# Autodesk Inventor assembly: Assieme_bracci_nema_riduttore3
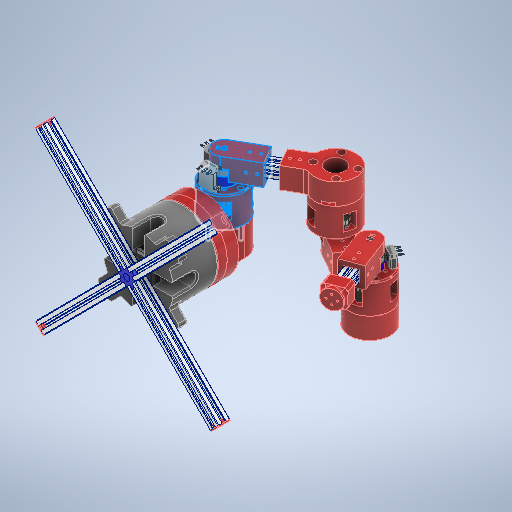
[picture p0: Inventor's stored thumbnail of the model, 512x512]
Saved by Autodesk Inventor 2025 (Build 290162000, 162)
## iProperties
Created: 2026-01
Part Number: Assieme_bracci_nema_riduttore3
Document SubType Name: Assembly
Designer: Ryzen5700u
Author: Ryzen5700u
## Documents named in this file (22)
- C:\Users\Ryzen5700u\Desktop\antropomorfo_nema5\Assieme_bracci_nema_riduttore4.iam
- C:\Users\Ryzen5700u\Desktop\antropomorfo_nema5\blocco_nema_riduttore.iam
- C:\Users\Ryzen5700u\Desktop\antropomorfo_nema5\blocco_nema2.ipt
- C:\Users\Ryzen5700u\Desktop\antropomorfo_nema5\blocco_nema_riduttore2.iam
- C:\Users\Ryzen5700u\Desktop\antropomorfo_nema5\blocco_base.ipt
- C:\Users\Ryzen5700u\Desktop\antropomorfo_nema5\tslot-20x20-5.ipt
- C:\Users\Ryzen5700u\Desktop\antropomorfo_nema5\terminale.ipt
- C:\Users\Ryzen5700u\Desktop\antropomorfo_nema5\NEMA 17HS4401S-PG518.ipt
- C:\Users\Ryzen5700u\Desktop\antropomorfo_nema5\base_01.ipt
- C:\Users\Ryzen5700u\Desktop\antropomorfo_nema5\maschera.ipt
- C:\Users\Ryzen5700u\Desktop\antropomorfo_nema5\ISO 104 - 1 11 50 x 70 x 14.ipt
- C:\Users\Ryzen5700u\Desktop\antropomorfo_nema5\blocco_alto_base.ipt
- C:\Users\Ryzen5700u\Documents\Inventor\Content Center Files\R2025\it-IT\AS 1112 (2)\AS 1112 - M5  Tipo 5.ipt
- C:\Users\Ryzen5700u\Desktop\antropomorfo_nema5\ANSI B18.3.1M - M5x0,8 x 30(1).ipt
- C:\Users\Ryzen5700u\Desktop\antropomorfo_nema5\Assieme_tappo_tslot.iam
- C:\Users\Ryzen5700u\Desktop\antropomorfo_nema5\tslot-20x20-4.ipt
- C:\Users\Ryzen5700u\Documents\Inventor\Content Center Files\R2025\it-IT\ANSI B18.3.1M(6)\ANSI B18.3.1M - M5x0,8 x 16(1).ipt
- C:\Users\Ryzen5700u\Desktop\antropomorfo_nema5\Microswitch-SS-3GL13SL\Microswitch-SS-3GL13SL.iam
- C:\Users\Ryzen5700u\Desktop\antropomorfo_nema5\blocco_finecorsa.ipt
- C:\Users\Ryzen5700u\Desktop\antropomorfo_nema5\blocco_finecorsa2.ipt
- C:\Users\Ryzen5700u\Desktop\antropomorfo_nema5\blocco_finecorsa3.ipt
- C:\Users\Ryzen5700u\Desktop\antropomorfo_nema5\b_sensore_1.ipt
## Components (36 placed, 21 different names)
1. tslot-20x20-4:2 — Coincidente:12, Coincidente:13, Coincidente:14, Coincidente:26, Coincidente:27, Coincidente:28
2. blocco_nema_riduttore2:3 [sub-assembly] — Coincidente:38, Coincidente:41, Coincidente:43, Coincidente:44, Coincidente:45, Coincidente:46, Rotazionale:7
3. blocco_nema_riduttore:2 [sub-assembly]
4. blocco_base:1
5. tslot-20x20-5:1 — Coincidente:32, Coincidente:33, Coincidente:34, Coincidente:35, Coincidente:36, Coincidente:37
6. blocco_nema2:1
7. blocco_nema_riduttore2:4 [sub-assembly]
8. blocco_nema2:2 — Coincidente:35, Coincidente:36, Coincidente:37, Coincidente:38, Coincidente:41, Coincidente:46, Angolo:10
9. tslot-20x20-4:1 — Coincidente:43, Coincidente:44, Coincidente:45, Coincidente:47, Coincidente:48, Coincidente:49
10. terminale:1 — Coincidente:47, Coincidente:48, Coincidente:49
11. NEMA 17HS4401S-PG518:1 — Angolo:3, Coincidente:56, Coincidente:57
12. base_01:1
13. maschera:1
14. UNI ISO 104 1 11 50 x 70 x 14:2 — Rotazionale:4, Coincidente:54
15. blocco_alto_base:2 — Coincidente:54, Coincidente:55, Angolo:5, Coincidente:59
16. Vite forgiata a testa incassata - Metrico M5x0,8 x 30:1
17. Vite forgiata a testa incassata - Metrico M5x0,8 x 30:2
18. Vite forgiata a testa incassata - Metrico M5x0,8 x 30:3
19. Vite forgiata a testa incassata - Metrico M5x0,8 x 30:4
20. Vite forgiata a testa incassata - Metrico M5x0,8 x 16:1
21. Vite forgiata a testa incassata - Metrico M5x0,8 x 16:4
22. Vite forgiata a testa incassata - Metrico M5x0,8 x 16:2
23. Vite forgiata a testa incassata - Metrico M5x0,8 x 16:3
24. Assieme_tappo_tslot:1 [sub-assembly] — Coincidente:60, Coincidente:61
25. Microswitch-SS-3GL13SL:1 [sub-assembly] — Angolo:6, Coincidente:62, Allineato:1, Allineato:2
26. blocco_finecorsa:1 — Rotazionale:5, Coincidente:62, Allineato:1, Allineato:2
27. blocco_finecorsa2:1 — Rotazionale:6, Coincidente:63, Angolo:9, Allineato:3, Allineato:4, Angolo:11
28. Microswitch-SS-3GL13SL:2 [sub-assembly] — Coincidente:63, Angolo:9, Allineato:3, Allineato:4
29. blocco_finecorsa3:1 — Rotazionale:7, Coincidente:64, Coincidente:65, Coincidente:66, Angolo:10
30. Microswitch-SS-3GL13SL:3 [sub-assembly] — Coincidente:64, Coincidente:65, Coincidente:66
31. b_sensore_1:3 — Rotazionale:8, Coincidente:67, Angolo:12, Allineato:5, Coincidente:68
32. Microswitch-SS-3GL13SL:4 [sub-assembly] — Coincidente:67, Angolo:12, Allineato:5, Coincidente:68
33. AS 1112 (2) - Metrico M5  Tipo 5:1
34. AS 1112 (2) - Metrico M5  Tipo 5:2
35. AS 1112 (2) - Metrico M5  Tipo 5:3
36. AS 1112 (2) - Metrico M5  Tipo 5:4
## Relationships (52: Mate 35, Angle 7, RevoluteJoint 5, Flush 5)
- Coincidente:12 [Mate]: tslot-20x20-4:2
- Coincidente:13 [Mate]: tslot-20x20-4:2
- Coincidente:14 [Mate]: tslot-20x20-4:2
- Coincidente:26 [Mate]: tslot-20x20-4:2
- Coincidente:27 [Mate]: tslot-20x20-4:2
- Coincidente:28 [Mate]: tslot-20x20-4:2
- Coincidente:32 [Mate]: tslot-20x20-5:1
- Coincidente:33 [Mate]: tslot-20x20-5:1
- Coincidente:34 [Mate]: tslot-20x20-5:1
- Coincidente:35 [Mate]: tslot-20x20-5:1 ↔ blocco_nema2:2
- Coincidente:36 [Mate]: tslot-20x20-5:1 ↔ blocco_nema2:2
- Coincidente:37 [Mate]: tslot-20x20-5:1 ↔ blocco_nema2:2
- Coincidente:38 [Mate]: blocco_nema_riduttore2:3 ↔ blocco_nema2:2
- Coincidente:41 [Mate]: blocco_nema_riduttore2:3 ↔ blocco_nema2:2
- Coincidente:43 [Mate]: blocco_nema_riduttore2:3 ↔ tslot-20x20-4:1
- Coincidente:44 [Mate]: blocco_nema_riduttore2:3 ↔ tslot-20x20-4:1
- Coincidente:45 [Mate]: blocco_nema_riduttore2:3 ↔ tslot-20x20-4:1
- Coincidente:46 [Mate]: blocco_nema_riduttore2:3 ↔ blocco_nema2:2
- Coincidente:47 [Mate]: tslot-20x20-4:1 ↔ terminale:1
- Coincidente:48 [Mate]: tslot-20x20-4:1 ↔ terminale:1
- Coincidente:49 [Mate]: tslot-20x20-4:1 ↔ terminale:1
- Rotazionale:4 [RevoluteJoint]: UNI ISO 104 1 11 50 x 70 x 14:2
- Angolo:3 [Angle]: NEMA 17HS4401S-PG518:1
- Coincidente:54 [Mate]: UNI ISO 104 1 11 50 x 70 x 14:2 ↔ blocco_alto_base:2
- Coincidente:55 [Mate]: blocco_alto_base:2
- Angolo:5 [Angle]: blocco_alto_base:2
- Coincidente:56 [Mate]: NEMA 17HS4401S-PG518:1
- Coincidente:57 [Mate]: NEMA 17HS4401S-PG518:1
- Coincidente:59 [Mate]: blocco_alto_base:2
- Coincidente:60 [Mate]: Assieme_tappo_tslot:1
- Coincidente:61 [Mate]: Assieme_tappo_tslot:1
- Angolo:6 [Angle]: Microswitch-SS-3GL13SL:1
- Rotazionale:5 [RevoluteJoint]: blocco_finecorsa:1
- Coincidente:62 [Mate]: Microswitch-SS-3GL13SL:1 ↔ blocco_finecorsa:1
- Allineato:1 [Flush]: Microswitch-SS-3GL13SL:1 ↔ blocco_finecorsa:1
- Allineato:2 [Flush]: Microswitch-SS-3GL13SL:1 ↔ blocco_finecorsa:1
- Rotazionale:6 [RevoluteJoint]: blocco_finecorsa2:1
- Coincidente:63 [Mate]: blocco_finecorsa2:1 ↔ Microswitch-SS-3GL13SL:2
- Angolo:9 [Angle]: blocco_finecorsa2:1 ↔ Microswitch-SS-3GL13SL:2
- Allineato:3 [Flush]: blocco_finecorsa2:1 ↔ Microswitch-SS-3GL13SL:2
- Allineato:4 [Flush]: blocco_finecorsa2:1 ↔ Microswitch-SS-3GL13SL:2
- Rotazionale:7 [RevoluteJoint]: blocco_nema_riduttore2:3 ↔ blocco_finecorsa3:1
- Coincidente:64 [Mate]: blocco_finecorsa3:1 ↔ Microswitch-SS-3GL13SL:3
- Coincidente:65 [Mate]: blocco_finecorsa3:1 ↔ Microswitch-SS-3GL13SL:3
- Coincidente:66 [Mate]: blocco_finecorsa3:1 ↔ Microswitch-SS-3GL13SL:3
- Angolo:10 [Angle]: blocco_nema2:2 ↔ blocco_finecorsa3:1
- Angolo:11 [Angle]: blocco_finecorsa2:1
- Rotazionale:8 [RevoluteJoint]: b_sensore_1:3
- Coincidente:67 [Mate]: b_sensore_1:3 ↔ Microswitch-SS-3GL13SL:4
- Angolo:12 [Angle]: b_sensore_1:3 ↔ Microswitch-SS-3GL13SL:4
- Allineato:5 [Flush]: b_sensore_1:3 ↔ Microswitch-SS-3GL13SL:4
- Coincidente:68 [Mate]: b_sensore_1:3 ↔ Microswitch-SS-3GL13SL:4
